(* Logix 5000 project; controller LD_Scale_Value 1756-L63 rev 16.7; software revision 16.00 *)

TASK MainTask (periodic, rate 5000 ms, priority 10, watchdog 500 ms) : AddOn_Instruction_Examples, Subroutine_Examples

MODULES
   Local : 1756-L63 (ICP 3, rev 16.7)
END_MODULES

TYPE SCLP_DINT_DT :
STRUCT
   Input : DINT;
   InputMin : DINT;
   InpuMax : DINT;
   ScaledMin : DINT;
   ScaledMax : DINT;
   Output : DINT;
   Local_Out : REAL;
   Local_Rate : REAL;
   Local_Offset : REAL;
   Local_Temp1 : REAL;
   Local_Temp2 : REAL;
   Local_Temp3 : REAL;
   Local_Temp4 : REAL;
END_STRUCT
END_TYPE

TYPE SCLP_REAL_DT :
STRUCT
   Input : REAL;
   InputMin : REAL;
   InpuMax : REAL;
   ScaledMin : REAL;
   ScaledMax : REAL;
   Output : REAL;
   Local_Rate : REAL;
   Local_Offset : REAL;
   Local_Temp1 : REAL;
   Local_Temp2 : REAL;
   Local_Temp3 : REAL;
   Local_Temp4 : REAL;
END_STRUCT
END_TYPE

TYPE SCLR_DINT_DT :   // Destination = (Source x Rate) + Offset
STRUCT
   Source : DINT;   // Input Value to be scaled
   Rate : DINT;   // (or slope) is the positive or negative value you enter divided by 10,000.
   Offset : DINT;
   Destination : DINT;   // Resulting Scaled Value
   Local_Temp1 : DINT;
END_STRUCT
END_TYPE

TYPE SCLR_REAL_DT :   // Destination = (Source x Rate) + Offset
STRUCT
   Source : REAL;   // Input Value to be scaled
   Rate : REAL;   // (or slope) is the positive or negative value you enter divided by 10,000.
   Offset : REAL;
   Destination : REAL;   // Resulting Scaled Value
END_STRUCT
END_TYPE

ADD_ON_INSTRUCTION SCLP   (* revision 1.0 *)
// Scale with Parameters
// Help:
// This routine performs the operation of the SLC-500 Scale With Parameters instruction (SCP).
// This output instruction consists of six parameters.  Parameters may be floating point or integer immediate data values or tags containing values.  The Input value is scaled to a range determined by creating a linear relationship between input min and max values and scaled min and max values.  The scaled result is returned to the tag indicated by the output parameter.
// The formula is as follows:
// Scaled value = (input value x rate) + offset
// Rate = (scaled max. - scaled min.) / (input max. - input min.)
// Offset = scaled minimum - (input minimum x rate)
// Note: The input minimum, input maximum, scaled minimum, and scaled maximum are used to determine the slope and offset values. The input value can go outside of the specified input limits and no ordering is required. For example, the scaled output value will not necessarily be clamped between the scaled minimum and scaled maximum values.
VAR_INPUT
   Input : REAL; {required}   // Value to be scaled
   InputMin : REAL; {required}   // Minimum value for the input (low end of range)
   InputMax : REAL; {required}   // Maximum value for the input (upper end of range)
   ScaledMin : REAL; {required}   // Minimum scaling value representing the low end of the linear range to which you want to scale the input
   ScaledMax : REAL; {required}   // Maximum scaling value representing the upper end of the linear range to which you want to scale the input
END_VAR
VAR_OUTPUT
   Output : REAL; {required}   // Resulting scaled value that is returned after the instruction is executed
END_VAR
VAR
   Temp1 : REAL;
   Temp2 : REAL;
   Rate : REAL;
   Temp4 : REAL;
   Offset : REAL;
   Temp3 : REAL;
END_VAR

ROUTINE Logic   (* ladder *)
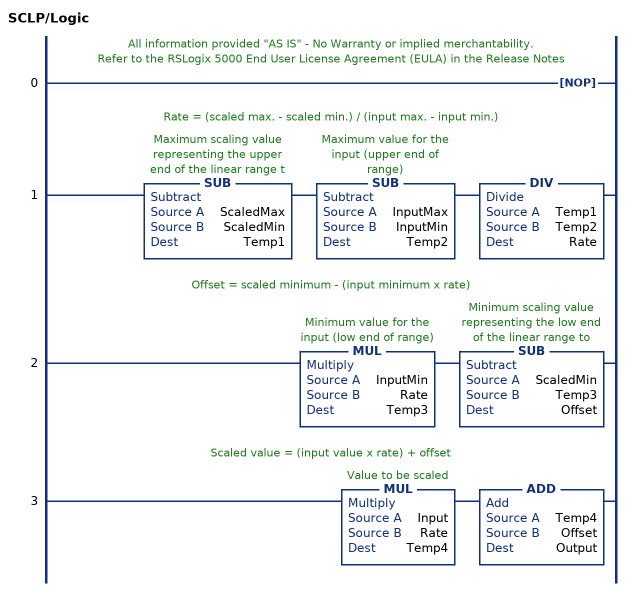
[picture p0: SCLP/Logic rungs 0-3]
   // All information provided "AS IS" - No Warranty or implied merchantability.
   // Refer to the RSLogix 5000 End User License Agreement (EULA) in the Release Notes
   0: NOP();
   // Rate = (scaled max. - scaled min.) / (input max. - input min.)
   1: SUB(ScaledMax,ScaledMin,Temp1)SUB(InputMax,InputMin,Temp2)DIV(Temp1,Temp2,Rate);
   // Offset = scaled minimum - (input minimum x rate)
   2: MUL(InputMin,Rate,Temp3)SUB(ScaledMin,Temp3,Offset);
   // Scaled value = (input value x rate) + offset
   3: MUL(Input,Rate,Temp4)ADD(Temp4,Offset,Output);
END_ROUTINE
END_ADD_ON_INSTRUCTION

ADD_ON_INSTRUCTION SCLR   (* revision 1.0 *)
// Scale with Rate
// Help:
// All information provided "AS IS" - No Warranty or implied merchantability.
// Refer to the RSLogix 5000 End User License Agreement (EULA) in the Release Notes
// This routine performs the operation of the SLC-500 Scale With Parameters instruction (SCL).
// Description:
// Use this instruction to scale data from your analog module and bring it into the limits prescribed by the process variable or another analog module. For example, use SCL to convert a 4-20 mA input signal to a PID process variable. Or use SCL to scale an analog input to control an analog output.
// When rung conditions are true, this instruction multiplies the source by a specified rate. The rounded result is added to an offset value and placed in the destination.
// Equations used in calculating a linear relationship:
// Scaled value = (input value x rate) + offset
// Rate = (scaled max. - scaled min.) / (input max. - input min.)
// Offset = scaled minimum - (input minimum x rate)
VAR_INPUT
   Source : REAL; {required}   // Input Value to be scaled
   Rate : REAL; {required}   // +/- value multiplied against source to represent the rate of change or slop of the desired output range
   Offset : REAL; {required}   // +/- Value to adjust result after rate is applied
END_VAR
VAR_OUTPUT
   Destination : REAL; {required}   // Resulting Scaled Value
END_VAR
VAR
   Temp : REAL;
END_VAR

ROUTINE Logic   (* ladder *)
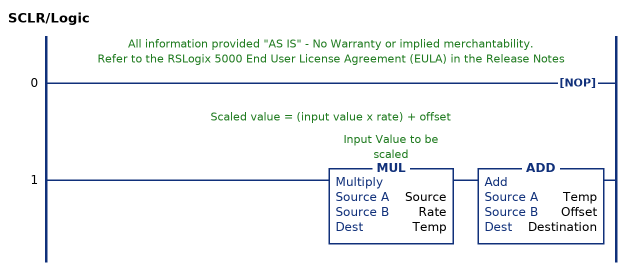
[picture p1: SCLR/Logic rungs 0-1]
   // All information provided "AS IS" - No Warranty or implied merchantability.
   // Refer to the RSLogix 5000 End User License Agreement (EULA) in the Release Notes
   0: NOP();
   // Scaled value = (input value x rate) + offset
   1: MUL(Source,Rate,Temp)ADD(Temp,Offset,Destination);
END_ROUTINE
END_ADD_ON_INSTRUCTION

PROGRAM AddOn_Instruction_Examples   (* main routine AOI_Call_Examples *)
VAR
   SCLP_DINT : SCLP := (Input := 1023.0, InputMax := 1024.0, ScaledMax := 100.0, Output := 99.90234);
   SCLP_DINT_Input : DINT := 1023;
   SCLP_DINT_Output : DINT := 100;
   SCLP_REAL : SCLP := (InputMax := 1024.0, ScaledMax := 100.0);
   SCLP_REAL_Input : REAL;
   SCLP_REAL_Output : REAL;
   SCLR_DINT : SCLR := (Source := 10.0, Rate := 50.0, Offset := 100.0, Destination := 600.0);
   SCLR_DINT_Input : DINT := 10;
   SCLR_DINT_Output : DINT := 600;
   SCLR_REAL : SCLR := (Rate := 50.0, Offset := 100.0, Destination := 100.0);
   SCLR_REAL_Input : REAL;
   SCLR_REAL_Output : REAL := 100.0;
END_VAR

ROUTINE AOI_Call_Examples   (* ladder *)
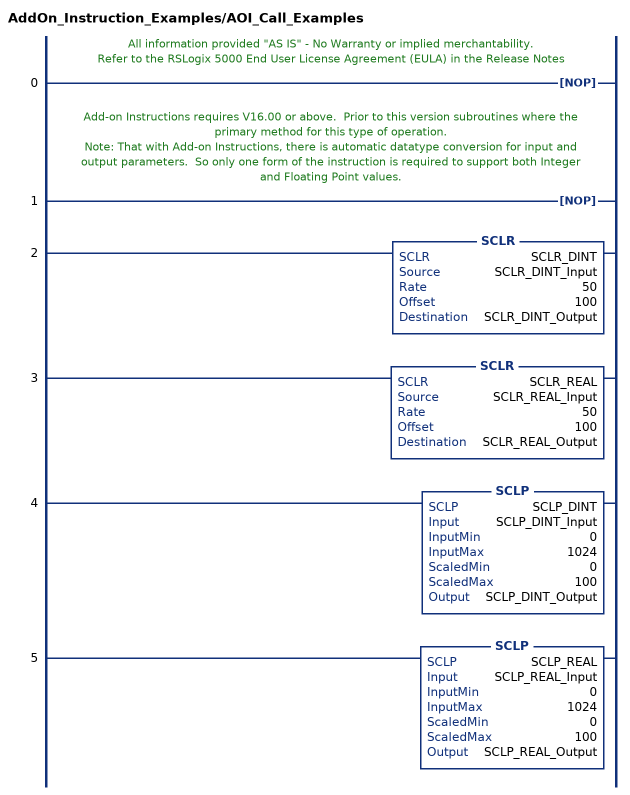
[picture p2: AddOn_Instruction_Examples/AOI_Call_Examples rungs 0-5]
   // All information provided "AS IS" - No Warranty or implied merchantability.
   // Refer to the RSLogix 5000 End User License Agreement (EULA) in the Release Notes
   0: NOP();
   // Add-on Instructions requires V16.00 or above.  Prior to this version subroutines where the primary method for this type of operation.
   // Note: That with Add-on Instructions, there is automatic datatype conversion for input and output parameters.  So only one form of the instruction is required to support both Integer and Floating Point values.
   1: NOP();
   2: SCLR(SCLR_DINT,SCLR_DINT_Input,50,100,SCLR_DINT_Output);
   3: SCLR(SCLR_REAL,SCLR_REAL_Input,50,100,SCLR_REAL_Output);
   4: SCLP(SCLP_DINT,SCLP_DINT_Input,0,1024,0,100,SCLP_DINT_Output);
   5: SCLP(SCLP_REAL,SCLP_REAL_Input,0,1024,0,100,SCLP_REAL_Output);
END_ROUTINE
END_PROGRAM

PROGRAM Compute_Examples
VAR
   SCL_CPT_Input : REAL;
   SCL_CPT_Offset : REAL;
   SCL_CPT_Output : REAL;
   SCL_CPT_Rate : REAL;
   SCP_CPT_InMax : DINT;
   SCP_CPT_InMin : DINT;
   SCP_CPT_Input : DINT;
   SCP_CPT_Output : DINT;
   SCP_CPT_SclMax : DINT;
   SCP_CPT_SclMin : DINT;
END_VAR

ROUTINE SCL_CPT_Example   (* ladder *)
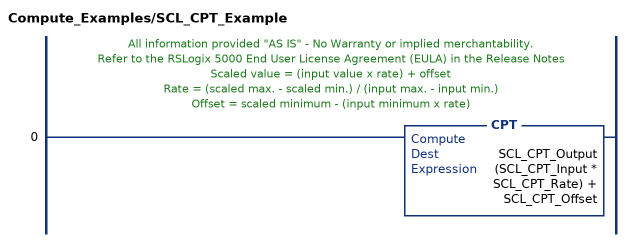
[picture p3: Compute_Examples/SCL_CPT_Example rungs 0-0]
   // All information provided "AS IS" - No Warranty or implied merchantability.
   // Refer to the RSLogix 5000 End User License Agreement (EULA) in the Release Notes
   // Scaled value = (input value x rate) + offset
   // Rate = (scaled max. - scaled min.) / (input max. - input min.)
   // Offset = scaled minimum - (input minimum x rate)
   0: CPT(SCL_CPT_Output,(SCL_CPT_Input * SCL_CPT_Rate) + SCL_CPT_Offset);
END_ROUTINE

ROUTINE SCP_CPT_Example   (* ladder *)
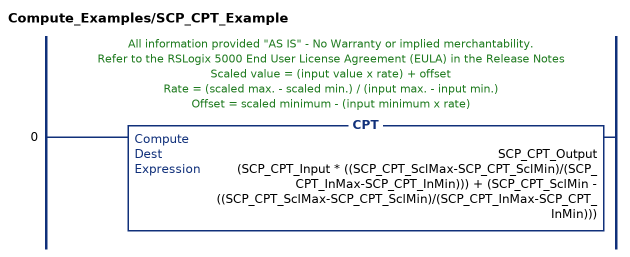
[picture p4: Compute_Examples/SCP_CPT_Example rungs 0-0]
   // All information provided "AS IS" - No Warranty or implied merchantability.
   // Refer to the RSLogix 5000 End User License Agreement (EULA) in the Release Notes
   // Scaled value = (input value x rate) + offset
   // Rate = (scaled max. - scaled min.) / (input max. - input min.)
   // Offset = scaled minimum - (input minimum x rate)
   0: CPT(SCP_CPT_Output,(SCP_CPT_Input * ((SCP_CPT_SclMax-SCP_CPT_SclMin)/(SCP_CPT_InMax-SCP_CPT_InMin))) + (SCP_CPT_SclMin - ((SCP_CPT_SclMax-SCP_CPT_SclMin)/(SCP_CPT_InMax-SCP_CPT_InMin))));
END_ROUTINE
END_PROGRAM

PROGRAM Subroutine_Examples   (* main routine MainRoutine *)
VAR
   SCLP_DINT : SCLP_DINT_DT := (InpuMax := 1024, ScaledMax := 100, Local_Rate := 0.09765625, Local_Temp1 := 100.0, Local_Temp2 := 1024.0);
   SCLP_DINT_Input : DINT;
   SCLP_DINT_Output : DINT;
   SCLP_REAL : SCLP_REAL_DT := (InpuMax := 1.435e-42, ScaledMax := 1.4e-43, Output := nan, Local_Rate := inf, Local_Offset := nan, Local_Temp3 := nan, Local_Temp4 := nan);
   SCLP_REAL_Input : REAL;
   SCLP_REAL_Output : REAL := nan;
   SCLR_DINT : SCLR_DINT_DT := (Rate := 50, Offset := 100);
   SCLR_DINT_Input : DINT;
   SCLR_DINT_Output : DINT := 100;
   SCLR_REAL : SCLR_REAL_DT := (Rate := 7.e-44, Offset := 1.4e-43);
   SCLR_REAL_Input : REAL;
   SCLR_REAL_Output : REAL;
END_VAR

ROUTINE MainRoutine   (* ladder *)
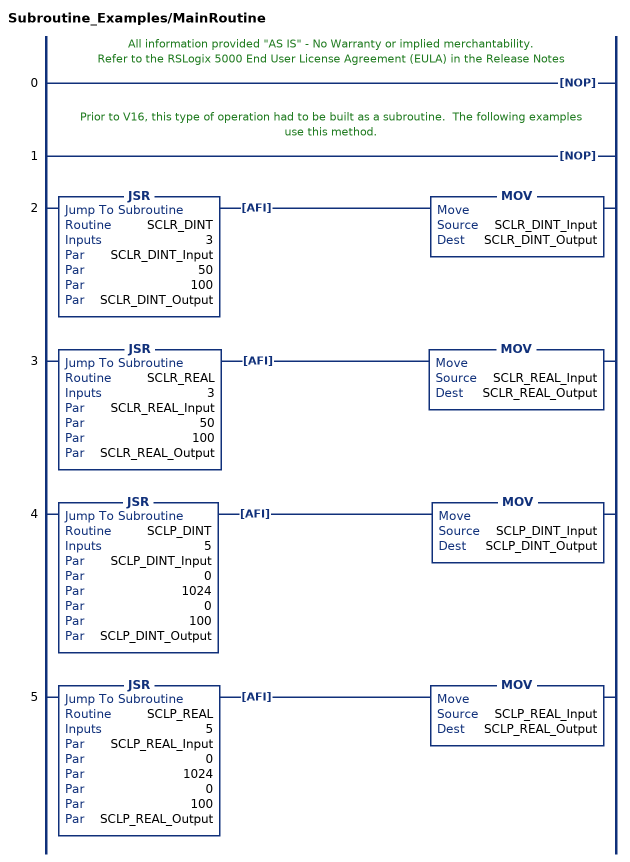
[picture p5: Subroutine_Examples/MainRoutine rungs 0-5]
   // All information provided "AS IS" - No Warranty or implied merchantability.
   // Refer to the RSLogix 5000 End User License Agreement (EULA) in the Release Notes
   0: NOP();
   // Prior to V16, this type of operation had to be built as a subroutine.  The following examples use this method.
   1: NOP();
   2: JSR(SCLR_DINT,3,SCLR_DINT_Input,50,100,SCLR_DINT_Output)AFI()MOV(SCLR_DINT_Input,SCLR_DINT_Output);
   3: JSR(SCLR_REAL,3,SCLR_REAL_Input,50,100,SCLR_REAL_Output)AFI()MOV(SCLR_REAL_Input,SCLR_REAL_Output);
   4: JSR(SCLP_DINT,5,SCLP_DINT_Input,0,1024,0,100,SCLP_DINT_Output)AFI()MOV(SCLP_DINT_Input,SCLP_DINT_Output);
   5: JSR(SCLP_REAL,5,SCLP_REAL_Input,0,1024,0,100,SCLP_REAL_Output)AFI()MOV(SCLP_REAL_Input,SCLP_REAL_Output);
END_ROUTINE

ROUTINE SCLP_DINT   (* ladder *)
// Scale with Prarams (all Real)
// In1=Source
// In2=InMin
// In3=InMax
// In4=ScaleMin
// In5=ScaleMax
// Out1=Destination
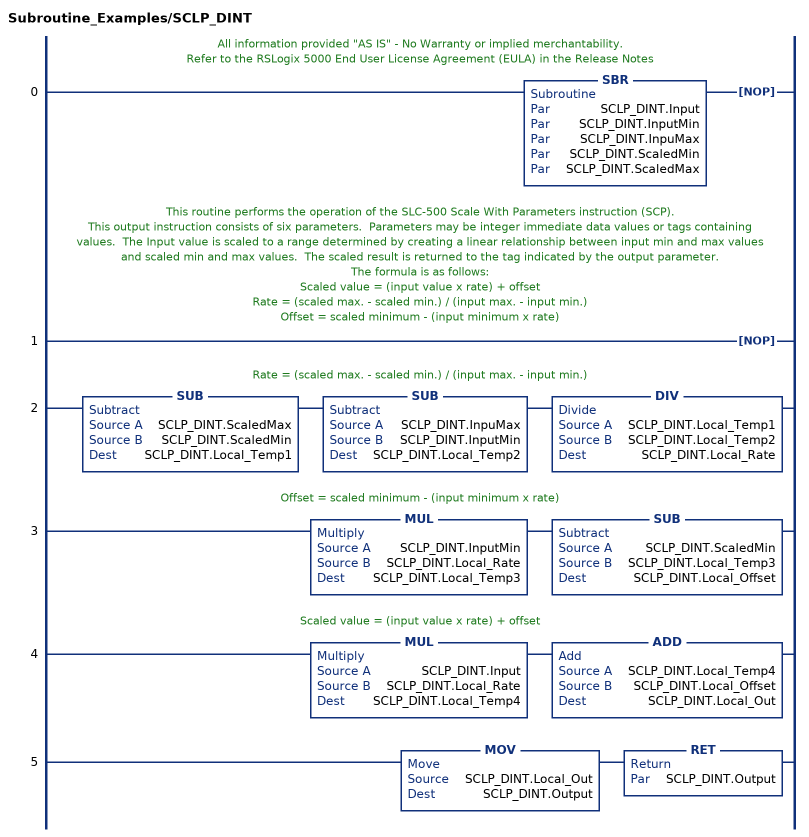
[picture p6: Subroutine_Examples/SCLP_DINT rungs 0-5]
   // All information provided "AS IS" - No Warranty or implied merchantability.
   // Refer to the RSLogix 5000 End User License Agreement (EULA) in the Release Notes
   0: SBR(SCLP_DINT.Input,SCLP_DINT.InputMin,SCLP_DINT.InpuMax,SCLP_DINT.ScaledMin,SCLP_DINT.ScaledMax)NOP();
   // This routine performs the operation of the SLC-500 Scale With Parameters instruction (SCP).
   // This output instruction consists of six parameters.  Parameters may be integer immediate data values or tags containing values.  The Input value is scaled to a range determined by creating a linear relationship between input min and max values and scaled min and max values.  The scaled result is returned to the tag indicated by the output parameter.
   // The formula is as follows:
   // Scaled value = (input value x rate) + offset
   // Rate = (scaled max. - scaled min.) / (input max. - input min.)
   // Offset = scaled minimum - (input minimum x rate)
   1: NOP();
   // Rate = (scaled max. - scaled min.) / (input max. - input min.)
   2: SUB(SCLP_DINT.ScaledMax,SCLP_DINT.ScaledMin,SCLP_DINT.Local_Temp1)SUB(SCLP_DINT.InpuMax,SCLP_DINT.InputMin,SCLP_DINT.Local_Temp2)DIV(SCLP_DINT.Local_Temp1,SCLP_DINT.Local_Temp2,SCLP_DINT.Local_Rate);
   // Offset = scaled minimum - (input minimum x rate)
   3: MUL(SCLP_DINT.InputMin,SCLP_DINT.Local_Rate,SCLP_DINT.Local_Temp3)SUB(SCLP_DINT.ScaledMin,SCLP_DINT.Local_Temp3,SCLP_DINT.Local_Offset);
   // Scaled value = (input value x rate) + offset
   4: MUL(SCLP_DINT.Input,SCLP_DINT.Local_Rate,SCLP_DINT.Local_Temp4)ADD(SCLP_DINT.Local_Temp4,SCLP_DINT.Local_Offset,SCLP_DINT.Local_Out);
   5: MOV(SCLP_DINT.Local_Out,SCLP_DINT.Output)RET(SCLP_DINT.Output);
END_ROUTINE

ROUTINE SCLP_REAL   (* ladder *)
// Scale with Params (all REAL)
// In1=Source
// In2=InMin
// In3=InMax
// In4=ScaleMin
// In5=ScaleMax
// Out1=Destination
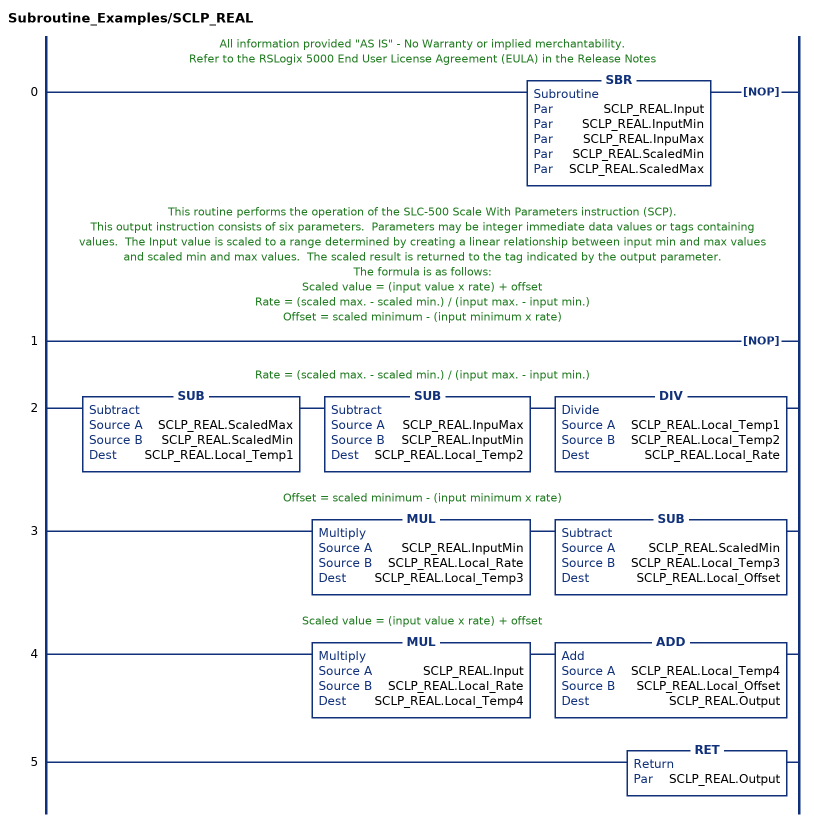
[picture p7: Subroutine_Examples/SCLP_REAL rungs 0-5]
   // All information provided "AS IS" - No Warranty or implied merchantability.
   // Refer to the RSLogix 5000 End User License Agreement (EULA) in the Release Notes
   0: SBR(SCLP_REAL.Input,SCLP_REAL.InputMin,SCLP_REAL.InpuMax,SCLP_REAL.ScaledMin,SCLP_REAL.ScaledMax)NOP();
   // This routine performs the operation of the SLC-500 Scale With Parameters instruction (SCP).
   // This output instruction consists of six parameters.  Parameters may be integer immediate data values or tags containing values.  The Input value is scaled to a range determined by creating a linear relationship between input min and max values and scaled min and max values.  The scaled result is returned to the tag indicated by the output parameter.
   // The formula is as follows:
   // Scaled value = (input value x rate) + offset
   // Rate = (scaled max. - scaled min.) / (input max. - input min.)
   // Offset = scaled minimum - (input minimum x rate)
   1: NOP();
   // Rate = (scaled max. - scaled min.) / (input max. - input min.)
   2: SUB(SCLP_REAL.ScaledMax,SCLP_REAL.ScaledMin,SCLP_REAL.Local_Temp1)SUB(SCLP_REAL.InpuMax,SCLP_REAL.InputMin,SCLP_REAL.Local_Temp2)DIV(SCLP_REAL.Local_Temp1,SCLP_REAL.Local_Temp2,SCLP_REAL.Local_Rate);
   // Offset = scaled minimum - (input minimum x rate)
   3: MUL(SCLP_REAL.InputMin,SCLP_REAL.Local_Rate,SCLP_REAL.Local_Temp3)SUB(SCLP_REAL.ScaledMin,SCLP_REAL.Local_Temp3,SCLP_REAL.Local_Offset);
   // Scaled value = (input value x rate) + offset
   4: MUL(SCLP_REAL.Input,SCLP_REAL.Local_Rate,SCLP_REAL.Local_Temp4)ADD(SCLP_REAL.Local_Temp4,SCLP_REAL.Local_Offset,SCLP_REAL.Output);
   5: RET(SCLP_REAL.Output);
END_ROUTINE

ROUTINE SCLR_DINT   (* ladder *)
// Scale Value
// (all DINT)
// In1=Source
// In2=Rate
// In3=Offset
// Out1=Destination
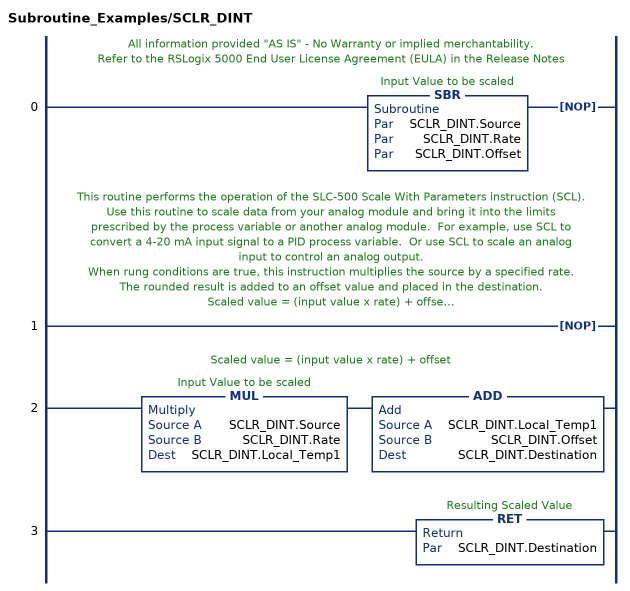
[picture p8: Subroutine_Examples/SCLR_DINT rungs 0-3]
   // All information provided "AS IS" - No Warranty or implied merchantability.
   // Refer to the RSLogix 5000 End User License Agreement (EULA) in the Release Notes
   0: SBR(SCLR_DINT.Source,SCLR_DINT.Rate,SCLR_DINT.Offset)NOP();
   // This routine performs the operation of the SLC-500 Scale With Parameters instruction (SCL).
   // Use this routine to scale data from your analog module and bring it into the limits prescribed by the process variable or another analog module.  For example, use SCL to convert a 4-20 mA input signal to a PID process variable.  Or use SCL to scale an analog input to control an analog output.
   // When rung conditions are true, this instruction multiplies the source by a specified rate.  The rounded result is added to an offset value and placed in the destination.
   // Scaled value = (input value x rate) + offset
   // Rate = (scaled max. - scaled min.) / (input max. - input min.)
   // Offset = scaled minimum - (input minimum x rate)
   1: NOP();
   // Scaled value = (input value x rate) + offset
   2: MUL(SCLR_DINT.Source,SCLR_DINT.Rate,SCLR_DINT.Local_Temp1)ADD(SCLR_DINT.Local_Temp1,SCLR_DINT.Offset,SCLR_DINT.Destination);
   3: RET(SCLR_DINT.Destination);
END_ROUTINE

ROUTINE SCLR_REAL   (* ladder *)
// Scale Value
// (all REAL)
// In1=Source
// In2=Rate
// In3=Offset
// Out1=Destination
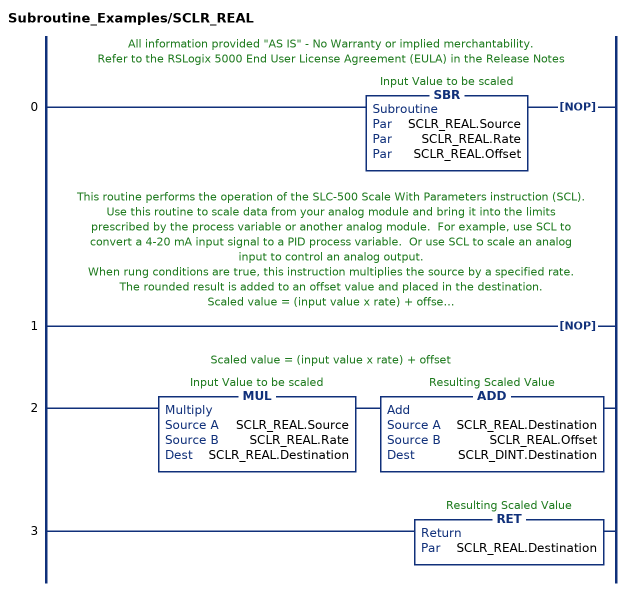
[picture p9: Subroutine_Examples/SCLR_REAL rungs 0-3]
   // All information provided "AS IS" - No Warranty or implied merchantability.
   // Refer to the RSLogix 5000 End User License Agreement (EULA) in the Release Notes
   0: SBR(SCLR_REAL.Source,SCLR_REAL.Rate,SCLR_REAL.Offset)NOP();
   // This routine performs the operation of the SLC-500 Scale With Parameters instruction (SCL).
   // Use this routine to scale data from your analog module and bring it into the limits prescribed by the process variable or another analog module.  For example, use SCL to convert a 4-20 mA input signal to a PID process variable.  Or use SCL to scale an analog input to control an analog output.
   // When rung conditions are true, this instruction multiplies the source by a specified rate.  The rounded result is added to an offset value and placed in the destination.
   // Scaled value = (input value x rate) + offset
   // Rate = (scaled max. - scaled min.) / (input max. - input min.)
   // Offset = scaled minimum - (input minimum x rate)
   1: NOP();
   // Scaled value = (input value x rate) + offset
   2: MUL(SCLR_REAL.Source,SCLR_REAL.Rate,SCLR_REAL.Destination)ADD(SCLR_REAL.Destination,SCLR_REAL.Offset,SCLR_DINT.Destination);
   3: RET(SCLR_REAL.Destination);
END_ROUTINE
END_PROGRAM
